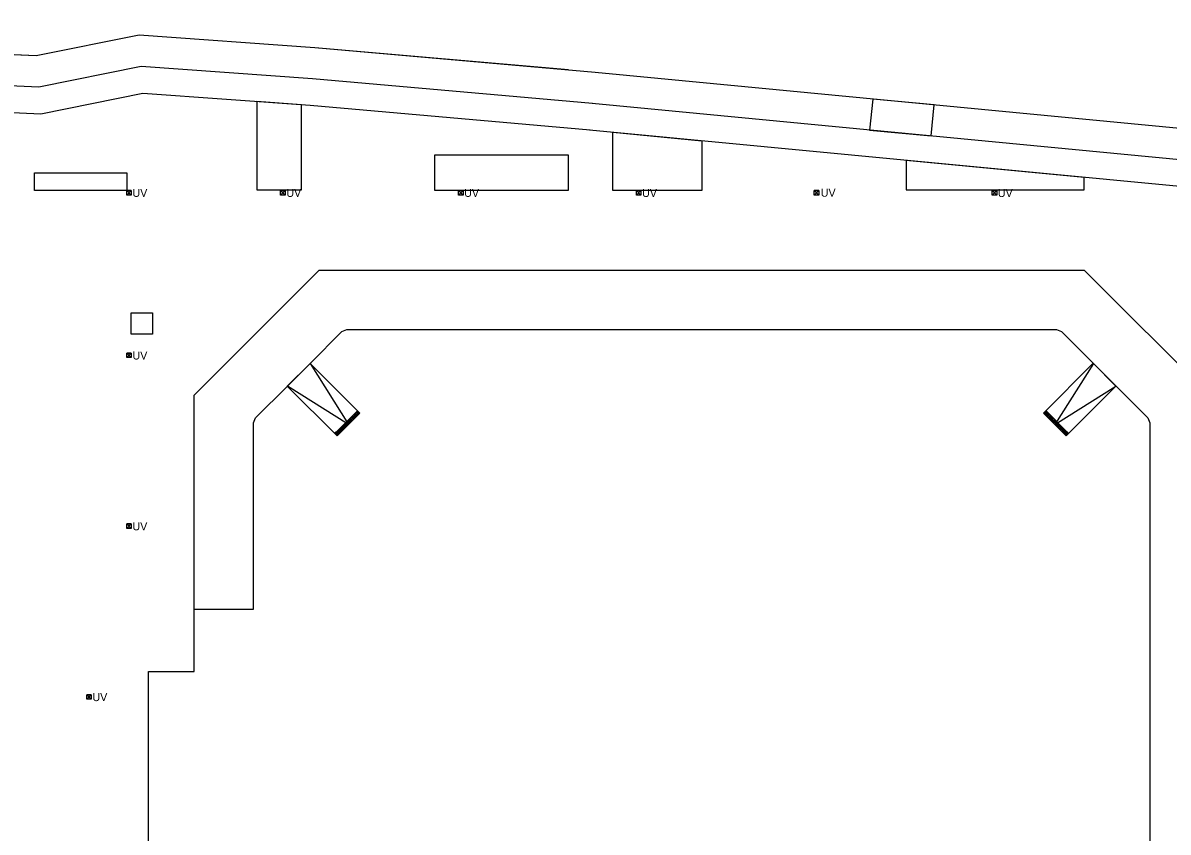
# Model space of a CAD drawing. Extents: x -264222 to -263676, y -1242344 to -1242060.
# Drawn here: x -263928.3 to -263799.5, y -1242150.5 to -1242059.5 of the extents above; entities that cross this region are included whole.
import ezdxf

# ---------------------------------------------------------------- set-up
doc = ezdxf.new("R2010")
doc.units = 0
doc.layers.add('PROJEKT_DRS_OBRUBNIKY_KOMUNIKACIE', color=7, linetype='Continuous')
doc.layers.add('PROJEKT_DRS_UV_STAVBY', color=7, linetype='Continuous')

msp = doc.modelspace()

# ---------------------------------------------------------------- linework, layer by layer
at = {"layer": 'PROJEKT_DRS_OBRUBNIKY_KOMUNIKACIE'}
for p, q in [((-263915.2, -1242060.92), (-263926.77, -1242063.25)), ((-263895.45, -1242062.32), (-263915.2, -1242060.92)), ((-263926.77, -1242063.25), (-263950.75, -1242062.15)), ((-263866.96, -1242064.82), (-263895.45, -1242062.32)), ((-263765.32, -1242074.56), (-263863.95, -1242065.11)), ((-263896.97, -1242068.73), (-263901.97, -1242068.38)), ((-263901.97, -1242068.38), (-263901.97, -1242074.38)), ((-263896.97, -1242074.38), (-263896.97, -1242068.73)), ((-263765.36, -1242078.08), (-263864.28, -1242068.59)), ((-263765.37, -1242081.09), (-263864.57, -1242071.58)), ((-263861.97, -1242078.38), (-263861.97, -1242071.83)), ((-263861.97, -1242071.83), (-263851.97, -1242072.79)), ((-263851.97, -1242072.79), (-263851.97, -1242078.38)), ((-263901.97, -1242074.38), (-263901.97, -1242078.31)), ((-263896.97, -1242078.31), (-263896.97, -1242074.38)), ((-263808.97, -1242076.91), (-263828.97, -1242074.99)), ((-263828.97, -1242074.99), (-263828.97, -1242078.31)), ((-263926.97, -1242076.38), (-263921.97, -1242076.38)), ((-263926.97, -1242078.38), (-263926.97, -1242076.38)), ((-263921.97, -1242076.38), (-263916.59, -1242076.38)), ((-263916.59, -1242076.38), (-263916.59, -1242078.38)), ((-263808.97, -1242078.31), (-263808.97, -1242076.91)), ((-263921.97, -1242078.38), (-263926.97, -1242078.38)), ((-263916.59, -1242078.38), (-263921.97, -1242078.38)), ((-263901.97, -1242078.31), (-263896.97, -1242078.31)), ((-263851.97, -1242078.38), (-263861.97, -1242078.38)), ((-263828.97, -1242078.31), (-263823.97, -1242078.31)), ((-263823.97, -1242078.31), (-263808.97, -1242078.31)), ((-263916.09, -1242092.11), (-263913.69, -1242092.11)), ((-263916.09, -1242094.51), (-263916.09, -1242092.11)), ((-263913.69, -1242092.11), (-263913.69, -1242094.51)), ((-263913.69, -1242094.51), (-263916.09, -1242094.51)), ((-263898.55, -1242100.36), (-263896, -1242097.81)), ((-263896, -1242097.81), (-263890.4, -1242103.42)), ((-263807.95, -1242097.8), (-263813.55, -1242103.41)), ((-263805.4, -1242100.35), (-263807.95, -1242097.8)), ((-263892.94, -1242105.96), (-263898.55, -1242100.36)), ((-263811.01, -1242105.95), (-263805.4, -1242100.35)), ((-263892.94, -1242105.96), (-263890.4, -1242103.42)), ((-263813.55, -1242103.41), (-263813.56, -1242103.4)), ((-263813.55, -1242103.41), (-263811.01, -1242105.95))]:
    msp.add_line(p, q, dxfattribs=at)
for points in [[(-263863.95, -1242065.11), (-263895.45, -1242062.32), (-263915.2, -1242060.92), (-263926.77, -1242063.25), (-263950.75, -1242062.15), (-263959.47, -1242059.53)], [(-263864.26, -1242068.59), (-263895.73, -1242065.81), (-263914.97, -1242064.45), (-263926.5, -1242066.77), (-263951.34, -1242065.63), (-263959.61, -1242063.14)], [(-263864.52, -1242071.58), (-263895.97, -1242068.8), (-263914.78, -1242067.47), (-263926.27, -1242069.78), (-263951.84, -1242068.6), (-263959.61, -1242066.28)], [(-263832.75, -1242068.1), (-263833.11, -1242071.58), (-263826.16, -1242072.24), (-263825.83, -1242068.75), (-263832.75, -1242068.1)], [(-263881.97, -1242074.38), (-263866.97, -1242074.38), (-263866.97, -1242078.38), (-263881.97, -1242078.38), (-263881.97, -1242074.38)], [(-263794.89, -1242227.38), (-263808.97, -1242241.46), (-263894.97, -1242241.46), (-263909.04, -1242227.38), (-263909.04, -1242196.33), (-263914.14, -1242196.33), (-263914.14, -1242132.43), (-263909.04, -1242132.43), (-263909.04, -1242101.38), (-263894.97, -1242087.31), (-263808.97, -1242087.31), (-263794.89, -1242101.38), (-263794.89, -1242227.38)], [(-263909.04, -1242125.43), (-263902.34, -1242125.43), (-263902.34, -1242104.48), (-263902.11, -1242103.93), (-263898.54, -1242100.36), (-263895.99, -1242097.81), (-263892.42, -1242094.24), (-263891.87, -1242094.01), (-263812.07, -1242094.01), (-263811.51, -1242094.24), (-263801.82, -1242103.93), (-263801.59, -1242104.48), (-263801.59, -1242224.28), (-263801.82, -1242224.84), (-263805.39, -1242228.41)], [(-263898.54, -1242100.36), (-263895.99, -1242097.81), (-263891.67, -1242104.69), (-263898.53, -1242100.37)], [(-263805.4, -1242100.35), (-263807.94, -1242097.81), (-263812.27, -1242104.69), (-263805.4, -1242100.37)]]:
    msp.add_lwpolyline(points, dxfattribs=at)
at = {"layer": 'PROJEKT_DRS_UV_STAVBY'}
for p, q in [((-263890.67, -1242103.13), (-263893.22, -1242105.68)), ((-263890.39, -1242103.41), (-263890.67, -1242103.13)), ((-263813.54, -1242103.41), (-263813.26, -1242103.13)), ((-263813.26, -1242103.13), (-263810.72, -1242105.68)), ((-263890.54, -1242103.28), (-263893.08, -1242105.82)), ((-263891.86, -1242104.6), (-263892, -1242104.46)), ((-263891.77, -1242104.51), (-263891.91, -1242104.37)), ((-263891.68, -1242104.42), (-263891.82, -1242104.28)), ((-263891.59, -1242104.34), (-263891.73, -1242104.19)), ((-263891.54, -1242104.56), (-263891.67, -1242104.42)), ((-263891.5, -1242104.25), (-263891.64, -1242104.1)), ((-263891.45, -1242104.47), (-263891.59, -1242104.33)), ((-263891.42, -1242104.16), (-263891.55, -1242104.01)), ((-263891.36, -1242104.38), (-263891.5, -1242104.24)), ((-263891.33, -1242104.07), (-263891.47, -1242103.93)), ((-263891.27, -1242104.3), (-263891.41, -1242104.15)), ((-263891.24, -1242103.98), (-263891.38, -1242103.84)), ((-263891.18, -1242104.21), (-263891.32, -1242104.06)), ((-263891.15, -1242103.89), (-263891.29, -1242103.75)), ((-263891.09, -1242104.12), (-263891.23, -1242103.98)), ((-263891.06, -1242103.8), (-263891.2, -1242103.66)), ((-263891, -1242104.03), (-263891.14, -1242103.89)), ((-263890.97, -1242103.72), (-263891.11, -1242103.57)), ((-263890.92, -1242103.94), (-263891.06, -1242103.8)), ((-263890.88, -1242103.63), (-263891.02, -1242103.48)), ((-263890.83, -1242103.85), (-263890.97, -1242103.71)), ((-263890.8, -1242103.54), (-263890.94, -1242103.4)), ((-263890.74, -1242103.77), (-263890.88, -1242103.62)), ((-263890.71, -1242103.45), (-263890.85, -1242103.31)), ((-263890.65, -1242103.68), (-263890.79, -1242103.53)), ((-263890.62, -1242103.36), (-263890.76, -1242103.22)), ((-263890.61, -1242103.35), (-263890.75, -1242103.21)), ((-263890.56, -1242103.59), (-263890.7, -1242103.45)), ((-263890.55, -1242103.58), (-263890.69, -1242103.44)), ((-263890.47, -1242103.5), (-263890.61, -1242103.36)), ((-263890.47, -1242103.49), (-263890.6, -1242103.35)), ((-263813.47, -1242103.49), (-263813.33, -1242103.35)), ((-263813.46, -1242103.5), (-263813.32, -1242103.36)), ((-263813.4, -1242103.28), (-263810.86, -1242105.82)), ((-263813.38, -1242103.58), (-263813.24, -1242103.44)), ((-263813.37, -1242103.59), (-263813.23, -1242103.45)), ((-263813.32, -1242103.35), (-263813.18, -1242103.21)), ((-263813.32, -1242103.36), (-263813.18, -1242103.22)), ((-263813.28, -1242103.68), (-263813.15, -1242103.53)), ((-263813.23, -1242103.45), (-263813.09, -1242103.31)), ((-263813.2, -1242103.77), (-263813.06, -1242103.62)), ((-263813.14, -1242103.54), (-263813, -1242103.4)), ((-263813.11, -1242103.85), (-263812.97, -1242103.71)), ((-263813.05, -1242103.63), (-263812.91, -1242103.48)), ((-263813.02, -1242103.94), (-263812.88, -1242103.8)), ((-263812.96, -1242103.72), (-263812.82, -1242103.57)), ((-263812.93, -1242104.03), (-263812.79, -1242103.89)), ((-263812.87, -1242103.8), (-263812.73, -1242103.66)), ((-263812.84, -1242104.12), (-263812.7, -1242103.98)), ((-263812.79, -1242103.89), (-263812.65, -1242103.75)), ((-263812.75, -1242104.21), (-263812.62, -1242104.06)), ((-263812.7, -1242103.98), (-263812.56, -1242103.84)), ((-263812.67, -1242104.3), (-263812.53, -1242104.15)), ((-263812.61, -1242104.07), (-263812.47, -1242103.93)), ((-263812.58, -1242104.38), (-263812.44, -1242104.24)), ((-263812.52, -1242104.16), (-263812.38, -1242104.01)), ((-263812.49, -1242104.47), (-263812.35, -1242104.33)), ((-263812.43, -1242104.25), (-263812.29, -1242104.1)), ((-263812.4, -1242104.56), (-263812.26, -1242104.42)), ((-263812.34, -1242104.34), (-263812.2, -1242104.19)), ((-263812.26, -1242104.42), (-263812.12, -1242104.28)), ((-263812.17, -1242104.51), (-263812.03, -1242104.37)), ((-263812.08, -1242104.6), (-263811.94, -1242104.46)), ((-263892.92, -1242105.66), (-263893.22, -1242105.67)), ((-263893.01, -1242105.76), (-263893.15, -1242105.61)), ((-263893.01, -1242105.75), (-263893.15, -1242105.61)), ((-263893.08, -1242105.82), (-263893.06, -1242105.52)), ((-263892.93, -1242105.67), (-263893.07, -1242105.53)), ((-263892.92, -1242105.66), (-263893.06, -1242105.52)), ((-263892.86, -1242105.89), (-263893, -1242105.74)), ((-263892.84, -1242105.58), (-263892.98, -1242105.44)), ((-263892.83, -1242105.57), (-263892.97, -1242105.43)), ((-263892.94, -1242105.96), (-263892.92, -1242105.66)), ((-263892.78, -1242105.81), (-263892.92, -1242105.66)), ((-263892.77, -1242105.8), (-263892.91, -1242105.66)), ((-263892.74, -1242105.48), (-263892.88, -1242105.34)), ((-263892.69, -1242105.72), (-263892.83, -1242105.58)), ((-263892.68, -1242105.71), (-263892.82, -1242105.57)), ((-263892.65, -1242105.4), (-263892.79, -1242105.25)), ((-263892.6, -1242105.62), (-263892.73, -1242105.48)), ((-263892.56, -1242105.31), (-263892.7, -1242105.16)), ((-263892.51, -1242105.53), (-263892.65, -1242105.39)), ((-263892.48, -1242105.22), (-263892.62, -1242105.07)), ((-263892.42, -1242105.44), (-263892.56, -1242105.3)), ((-263892.39, -1242105.13), (-263892.53, -1242104.99)), ((-263892.33, -1242105.36), (-263892.47, -1242105.21)), ((-263892.3, -1242105.04), (-263892.44, -1242104.9)), ((-263892.24, -1242105.27), (-263892.38, -1242105.12)), ((-263892.21, -1242104.95), (-263892.35, -1242104.81)), ((-263892.15, -1242105.18), (-263892.29, -1242105.04)), ((-263892.12, -1242104.87), (-263892.26, -1242104.72)), ((-263892.07, -1242105.09), (-263892.2, -1242104.95)), ((-263892.03, -1242104.78), (-263892.17, -1242104.63)), ((-263891.98, -1242105), (-263892.12, -1242104.86)), ((-263891.95, -1242104.69), (-263892.09, -1242104.54)), ((-263891.89, -1242104.91), (-263892.03, -1242104.77)), ((-263891.8, -1242104.83), (-263891.94, -1242104.68)), ((-263891.71, -1242104.74), (-263891.85, -1242104.59)), ((-263891.62, -1242104.65), (-263891.76, -1242104.51)), ((-263812.31, -1242104.65), (-263812.17, -1242104.51)), ((-263812.22, -1242104.74), (-263812.08, -1242104.59)), ((-263812.14, -1242104.83), (-263812, -1242104.68)), ((-263812.05, -1242104.91), (-263811.91, -1242104.77)), ((-263811.99, -1242104.69), (-263811.85, -1242104.54)), ((-263811.96, -1242105), (-263811.82, -1242104.86)), ((-263811.9, -1242104.78), (-263811.76, -1242104.63)), ((-263811.87, -1242105.09), (-263811.73, -1242104.95)), ((-263811.81, -1242104.87), (-263811.67, -1242104.72)), ((-263811.78, -1242105.18), (-263811.64, -1242105.04)), ((-263811.72, -1242104.95), (-263811.59, -1242104.81)), ((-263811.69, -1242105.27), (-263811.55, -1242105.12)), ((-263811.64, -1242105.04), (-263811.5, -1242104.9)), ((-263811.6, -1242105.36), (-263811.47, -1242105.21)), ((-263811.55, -1242105.13), (-263811.41, -1242104.99)), ((-263811.52, -1242105.44), (-263811.38, -1242105.3)), ((-263811.46, -1242105.22), (-263811.32, -1242105.07)), ((-263811.43, -1242105.53), (-263811.29, -1242105.39)), ((-263811.37, -1242105.31), (-263811.23, -1242105.16)), ((-263811.34, -1242105.62), (-263811.2, -1242105.48)), ((-263811.28, -1242105.4), (-263811.14, -1242105.25)), ((-263811.25, -1242105.71), (-263811.11, -1242105.57)), ((-263811.24, -1242105.72), (-263811.1, -1242105.58)), ((-263811.19, -1242105.48), (-263811.05, -1242105.34)), ((-263811.16, -1242105.8), (-263811.02, -1242105.66)), ((-263811.15, -1242105.81), (-263811.02, -1242105.66)), ((-263811.11, -1242105.57), (-263810.97, -1242105.43)), ((-263811.1, -1242105.58), (-263810.96, -1242105.44)), ((-263811.07, -1242105.89), (-263810.94, -1242105.74)), ((-263811.02, -1242105.66), (-263810.88, -1242105.52)), ((-263811.01, -1242105.67), (-263810.87, -1242105.53)), ((-263811, -1242105.96), (-263811.01, -1242105.66)), ((-263811.01, -1242105.66), (-263810.72, -1242105.67)), ((-263810.93, -1242105.75), (-263810.79, -1242105.61)), ((-263810.92, -1242105.76), (-263810.78, -1242105.61)), ((-263810.86, -1242105.82), (-263810.87, -1242105.52)), ((-263892.78, -1242105.8), (-263893.08, -1242105.82)), ((-263892.87, -1242105.9), (-263893.01, -1242105.75)), ((-263811.15, -1242105.8), (-263810.86, -1242105.82)), ((-263811.07, -1242105.9), (-263810.93, -1242105.75))]:
    msp.add_line(p, q, dxfattribs=at)
for points in [[(-263916.59, -1242078.88), (-263916.59, -1242078.38), (-263916.09, -1242078.38), (-263916.09, -1242078.88), (-263916.59, -1242078.88), (-263916.09, -1242078.38), (-263916.59, -1242078.38), (-263916.09, -1242078.88)], [(-263899.3, -1242078.88), (-263899.3, -1242078.38), (-263898.8, -1242078.38), (-263898.8, -1242078.88), (-263899.3, -1242078.88), (-263898.8, -1242078.38), (-263899.3, -1242078.38), (-263898.8, -1242078.88)], [(-263879.3, -1242078.88), (-263879.3, -1242078.38), (-263878.8, -1242078.38), (-263878.8, -1242078.88), (-263879.3, -1242078.88), (-263878.8, -1242078.38), (-263879.3, -1242078.38), (-263878.8, -1242078.88)], [(-263859.3, -1242078.88), (-263859.3, -1242078.38), (-263858.8, -1242078.38), (-263858.8, -1242078.88), (-263859.3, -1242078.88), (-263858.8, -1242078.38), (-263859.3, -1242078.38), (-263858.8, -1242078.88)], [(-263839.31, -1242078.88), (-263839.31, -1242078.38), (-263838.81, -1242078.38), (-263838.81, -1242078.88), (-263839.31, -1242078.88), (-263838.81, -1242078.38), (-263839.31, -1242078.38), (-263838.81, -1242078.88)], [(-263819.31, -1242078.88), (-263819.31, -1242078.38), (-263818.81, -1242078.38), (-263818.81, -1242078.88), (-263819.31, -1242078.88), (-263818.81, -1242078.38), (-263819.31, -1242078.38), (-263818.81, -1242078.88)], [(-263916.59, -1242097.16), (-263916.59, -1242096.66), (-263916.09, -1242096.66), (-263916.09, -1242097.16), (-263916.59, -1242097.16), (-263916.09, -1242096.66), (-263916.59, -1242096.66), (-263916.09, -1242097.16)], [(-263890.54, -1242103.28), (-263893.08, -1242105.82), (-263893.22, -1242105.68)], [(-263890.39, -1242103.41), (-263892.94, -1242105.96), (-263893.08, -1242105.82)], [(-263813.54, -1242103.41), (-263811, -1242105.96), (-263810.86, -1242105.82)], [(-263813.4, -1242103.28), (-263810.86, -1242105.82), (-263810.72, -1242105.68)], [(-263893.08, -1242105.82), (-263893.22, -1242105.68), (-263893.06, -1242105.52), (-263892.92, -1242105.66), (-263893.08, -1242105.82)], [(-263892.94, -1242105.96), (-263893.08, -1242105.82), (-263892.92, -1242105.66), (-263892.78, -1242105.8), (-263892.94, -1242105.96)], [(-263811, -1242105.96), (-263810.86, -1242105.82), (-263811.01, -1242105.66), (-263811.15, -1242105.8), (-263811, -1242105.96)], [(-263810.86, -1242105.82), (-263810.72, -1242105.68), (-263810.87, -1242105.52), (-263811.01, -1242105.66), (-263810.86, -1242105.82)], [(-263916.59, -1242116.36), (-263916.59, -1242115.86), (-263916.09, -1242115.86), (-263916.09, -1242116.36), (-263916.59, -1242116.36), (-263916.09, -1242115.86), (-263916.59, -1242115.86), (-263916.09, -1242116.36)], [(-263921.09, -1242135.56), (-263921.09, -1242135.06), (-263920.59, -1242135.06), (-263920.59, -1242135.56), (-263921.09, -1242135.56), (-263920.59, -1242135.06), (-263921.09, -1242135.06), (-263920.59, -1242135.56)]]:
    msp.add_lwpolyline(points, dxfattribs=at)

# ---------------------------------------------------------------- texts
for p in [(-263915.96, -1242079.09), (-263898.66, -1242079.09), (-263878.67, -1242079.09), (-263858.67, -1242079.1), (-263838.59, -1242079.07), (-263818.68, -1242079.1), (-263915.96, -1242097.37), (-263915.96, -1242116.57), (-263920.46, -1242135.77)]:
    msp.add_text('UV', height=0.9, rotation=359.8587, dxfattribs=at).set_placement(p)

doc.saveas('drawing.dxf')
